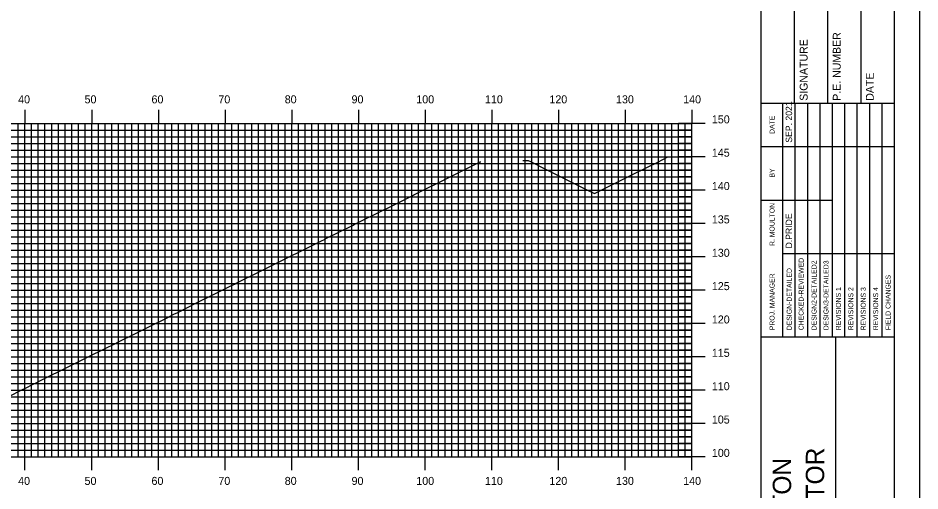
# Model space of a CAD drawing. Extents: x 1684799 to 1685142, y 461260 to 461480.
# Drawn here: x 1685003.7 to 1685138.9, y 461333 to 461403.9 of the extents above; entities that cross this region are included whole.
import ezdxf

# ---------------------------------------------------------------- set-up
doc = ezdxf.new("R2010")
doc.units = 0
for name, color, linetype in [('BORDER', 7, 'Continuous'), ('H_V ANNOTATION', 7, 'Continuous'), ('MAJOR', 7, 'Continuous'), ('MINOR', 7, 'Continuous'), ('PLOT BOUNDARY', 7, 'Continuous'), ('S_Roadway_Centerline', 7, 'Continuous')]:
    doc.layers.add(name, color=color, linetype=linetype)

msp = doc.modelspace()

# ---------------------------------------------------------------- linework, layer by layer
at = {"layer": 'BORDER'}
for p, q in [((1685115.12, 461266.07), (1685115.12, 461476.07)), ((1685120.12, 461391.08), (1685120.12, 461408.37)), ((1685125.12, 461391.08), (1685125.12, 461408.37)), ((1685130.12, 461391.08), (1685130.12, 461408.37)), ((1685115.12, 461391.08), (1685135.12, 461391.08)), ((1685115.12, 461356.08), (1685135.12, 461356.08)), ((1685126.3, 461286.08), (1685126.3, 461356.08))]:
    msp.add_line(p, q, dxfattribs=at)
msp.add_lwpolyline([(1684815.12, 461266.07), (1685135.12, 461266.07), (1685135.12, 461476.07), (1684815.12, 461476.07)], close=True, dxfattribs=at)
for points in [[(1685118.35, 461384.58), (1685118.35, 461391.08)], [(1685120.21, 461356.08), (1685120.21, 461391.08)], [(1685122.07, 461391.08), (1685122.07, 461356.08)], [(1685123.94, 461356.08), (1685123.94, 461391.08)], [(1685125.8, 461356.08), (1685125.8, 461391.08)], [(1685127.66, 461356.08), (1685127.66, 461391.08)], [(1685129.53, 461356.08), (1685129.53, 461391.08)], [(1685131.39, 461356.08), (1685131.39, 461391.08)], [(1685133.25, 461356.08), (1685133.25, 461391.08)], [(1685118.35, 461356.08), (1685118.35, 461389.67)], [(1685115.12, 461384.58), (1685135.12, 461384.58)], [(1685115.12, 461376.58), (1685118.35, 461376.58)], [(1685118.35, 461376.58), (1685125.8, 461376.58)], [(1685118.35, 461368.58), (1685135.12, 461368.58)]]:
    msp.add_lwpolyline(points, dxfattribs=at)
at = {"layer": 'MAJOR'}
for p, q in [((1685004.72, 461390.08), (1685004.72, 461388.07)), ((1685014.72, 461390.08), (1685014.72, 461388.07)), ((1685024.72, 461390.08), (1685024.72, 461388.07)), ((1685034.72, 461390.08), (1685034.72, 461388.07)), ((1685044.72, 461390.08), (1685044.72, 461388.07)), ((1685054.72, 461390.08), (1685054.72, 461388.07)), ((1685064.72, 461390.08), (1685064.72, 461388.07)), ((1685074.72, 461390.08), (1685074.72, 461388.07)), ((1685084.72, 461390.08), (1685084.72, 461388.07)), ((1685094.72, 461390.08), (1685094.72, 461388.07)), ((1685104.72, 461390.08), (1685104.72, 461388.07)), ((1684824.72, 461388.07), (1685104.72, 461388.07)), ((1684824.72, 461388.07), (1685104.72, 461388.07)), ((1685004.72, 461338.07), (1685004.72, 461388.07)), ((1685014.72, 461338.07), (1685014.72, 461388.07)), ((1685024.72, 461338.07), (1685024.72, 461388.07)), ((1685034.72, 461338.07), (1685034.72, 461388.07)), ((1685044.72, 461338.07), (1685044.72, 461388.07)), ((1685054.72, 461338.07), (1685054.72, 461388.07)), ((1685064.72, 461338.07), (1685064.72, 461388.07)), ((1685074.72, 461338.07), (1685074.72, 461388.07)), ((1685084.72, 461338.07), (1685084.72, 461388.07)), ((1685094.72, 461338.07), (1685094.72, 461388.07)), ((1685106.72, 461388.07), (1685102.71, 461388.07)), ((1685104.72, 461338.07), (1685104.72, 461388.07)), ((1685104.72, 461338.07), (1685104.72, 461388.07)), ((1684824.72, 461383.07), (1685104.72, 461383.07)), ((1685106.72, 461383.07), (1685102.71, 461383.07)), ((1684824.72, 461378.07), (1685104.72, 461378.07)), ((1685106.72, 461378.07), (1685102.71, 461378.07)), ((1684824.72, 461373.07), (1685104.72, 461373.07)), ((1685106.72, 461373.07), (1685102.71, 461373.07)), ((1684824.72, 461368.07), (1685104.72, 461368.07)), ((1685106.72, 461368.07), (1685102.71, 461368.07)), ((1684824.72, 461363.07), (1685104.72, 461363.07)), ((1685106.72, 461363.07), (1685102.71, 461363.07)), ((1684824.72, 461358.07), (1685104.72, 461358.07)), ((1685106.72, 461358.07), (1685102.71, 461358.07)), ((1684824.72, 461353.07), (1685104.72, 461353.07)), ((1685106.72, 461353.07), (1685102.71, 461353.07)), ((1684824.72, 461348.07), (1685104.72, 461348.07)), ((1685106.72, 461348.07), (1685102.71, 461348.07)), ((1684824.72, 461343.07), (1685104.72, 461343.07)), ((1685106.72, 461343.07), (1685102.71, 461343.07)), ((1684824.72, 461338.07), (1685104.72, 461338.07)), ((1684824.72, 461338.07), (1685104.72, 461338.07)), ((1685004.72, 461336.07), (1685004.72, 461338.07)), ((1685014.72, 461336.07), (1685014.72, 461338.07)), ((1685024.72, 461336.07), (1685024.72, 461338.07)), ((1685034.72, 461336.07), (1685034.72, 461338.07)), ((1685044.72, 461336.07), (1685044.72, 461338.07)), ((1685054.72, 461336.07), (1685054.72, 461338.07)), ((1685064.72, 461336.07), (1685064.72, 461338.07)), ((1685074.72, 461336.07), (1685074.72, 461338.07)), ((1685084.72, 461336.07), (1685084.72, 461338.07)), ((1685094.72, 461336.07), (1685094.72, 461338.07)), ((1685106.72, 461338.07), (1685102.71, 461338.07)), ((1685104.72, 461336.07), (1685104.72, 461338.07))]:
    msp.add_line(p, q, dxfattribs=at)
at = {"layer": 'MINOR'}
for p, q in [((1685003.72, 461338.07), (1685003.72, 461388.07)), ((1685005.72, 461338.07), (1685005.72, 461388.07)), ((1685006.72, 461338.07), (1685006.72, 461388.07)), ((1685007.72, 461338.07), (1685007.72, 461388.07)), ((1685008.72, 461338.07), (1685008.72, 461388.07)), ((1685009.72, 461338.07), (1685009.72, 461388.07)), ((1685010.72, 461338.07), (1685010.72, 461388.07)), ((1685011.72, 461338.07), (1685011.72, 461388.07)), ((1685012.72, 461338.07), (1685012.72, 461388.07)), ((1685013.72, 461338.07), (1685013.72, 461388.07)), ((1685015.72, 461338.07), (1685015.72, 461388.07)), ((1685016.72, 461338.07), (1685016.72, 461388.07)), ((1685017.72, 461338.07), (1685017.72, 461388.07)), ((1685018.72, 461338.07), (1685018.72, 461388.07)), ((1685019.72, 461338.07), (1685019.72, 461388.07)), ((1685020.72, 461338.07), (1685020.72, 461388.07)), ((1685021.72, 461338.07), (1685021.72, 461388.07)), ((1685022.72, 461338.07), (1685022.72, 461388.07)), ((1685023.72, 461338.07), (1685023.72, 461388.07)), ((1685025.72, 461338.07), (1685025.72, 461388.07)), ((1685026.72, 461338.07), (1685026.72, 461388.07)), ((1685027.72, 461338.07), (1685027.72, 461388.07)), ((1685028.72, 461338.07), (1685028.72, 461388.07)), ((1685029.72, 461338.07), (1685029.72, 461388.07)), ((1685030.72, 461338.07), (1685030.72, 461388.07)), ((1685031.72, 461338.07), (1685031.72, 461388.07)), ((1685032.72, 461338.07), (1685032.72, 461388.07)), ((1685033.72, 461338.07), (1685033.72, 461388.07)), ((1685035.72, 461338.07), (1685035.72, 461388.07)), ((1685036.72, 461338.07), (1685036.72, 461388.07)), ((1685037.72, 461338.07), (1685037.72, 461388.07)), ((1685038.72, 461338.07), (1685038.72, 461388.07)), ((1685039.72, 461338.07), (1685039.72, 461388.07)), ((1685040.72, 461338.07), (1685040.72, 461388.07)), ((1685041.72, 461338.07), (1685041.72, 461388.07)), ((1685042.72, 461338.07), (1685042.72, 461388.07)), ((1685043.72, 461338.07), (1685043.72, 461388.07)), ((1685045.72, 461338.07), (1685045.72, 461388.07)), ((1685046.72, 461338.07), (1685046.72, 461388.07)), ((1685047.72, 461338.07), (1685047.72, 461388.07)), ((1685048.72, 461338.07), (1685048.72, 461388.07)), ((1685049.72, 461338.07), (1685049.72, 461388.07)), ((1685050.72, 461338.07), (1685050.72, 461388.07)), ((1685051.72, 461338.07), (1685051.72, 461388.07)), ((1685052.72, 461338.07), (1685052.72, 461388.07)), ((1685053.72, 461338.07), (1685053.72, 461388.07)), ((1685055.72, 461338.07), (1685055.72, 461388.07)), ((1685056.72, 461338.07), (1685056.72, 461388.07)), ((1685057.72, 461338.07), (1685057.72, 461388.07)), ((1685058.72, 461338.07), (1685058.72, 461388.07)), ((1685059.72, 461338.07), (1685059.72, 461388.07)), ((1685060.72, 461338.07), (1685060.72, 461388.07)), ((1685061.72, 461338.07), (1685061.72, 461388.07)), ((1685062.72, 461338.07), (1685062.72, 461388.07)), ((1685063.72, 461338.07), (1685063.72, 461388.07)), ((1685065.72, 461338.07), (1685065.72, 461388.07)), ((1685066.72, 461338.07), (1685066.72, 461388.07)), ((1685067.72, 461338.07), (1685067.72, 461388.07)), ((1685068.72, 461338.07), (1685068.72, 461388.07)), ((1685069.72, 461338.07), (1685069.72, 461388.07)), ((1685070.72, 461338.07), (1685070.72, 461388.07)), ((1685071.72, 461338.07), (1685071.72, 461388.07)), ((1685072.72, 461338.07), (1685072.72, 461388.07)), ((1685073.72, 461338.07), (1685073.72, 461388.07)), ((1685075.72, 461338.07), (1685075.72, 461388.07)), ((1685076.72, 461338.07), (1685076.72, 461388.07)), ((1685077.72, 461338.07), (1685077.72, 461388.07)), ((1685078.72, 461338.07), (1685078.72, 461388.07)), ((1685079.72, 461338.07), (1685079.72, 461388.07)), ((1685080.72, 461338.07), (1685080.72, 461388.07)), ((1685081.72, 461338.07), (1685081.72, 461388.07)), ((1685082.72, 461338.07), (1685082.72, 461388.07)), ((1685083.72, 461338.07), (1685083.72, 461388.07)), ((1685085.72, 461338.07), (1685085.72, 461388.07)), ((1685086.72, 461338.07), (1685086.72, 461388.07)), ((1685087.72, 461338.07), (1685087.72, 461388.07)), ((1685088.72, 461338.07), (1685088.72, 461388.07)), ((1685089.72, 461338.07), (1685089.72, 461388.07)), ((1685090.72, 461338.07), (1685090.72, 461388.07)), ((1685091.72, 461338.07), (1685091.72, 461388.07)), ((1685092.72, 461338.07), (1685092.72, 461388.07)), ((1685093.72, 461338.07), (1685093.72, 461388.07)), ((1685095.72, 461338.07), (1685095.72, 461388.07)), ((1685096.72, 461338.07), (1685096.72, 461388.07)), ((1685097.72, 461338.07), (1685097.72, 461388.07)), ((1685098.72, 461338.07), (1685098.72, 461388.07)), ((1685099.72, 461338.07), (1685099.72, 461388.07)), ((1685100.72, 461338.07), (1685100.72, 461388.07)), ((1685101.72, 461338.07), (1685101.72, 461388.07)), ((1685102.72, 461338.07), (1685102.72, 461388.07)), ((1685103.72, 461338.07), (1685103.72, 461388.07)), ((1684824.72, 461387.07), (1685104.72, 461387.07)), ((1685104.72, 461387.07), (1685102.71, 461387.07)), ((1684824.72, 461386.07), (1685104.72, 461386.07)), ((1684824.72, 461385.07), (1685104.72, 461385.07)), ((1685104.72, 461386.07), (1685102.71, 461386.07)), ((1685104.72, 461385.07), (1685102.71, 461385.07)), ((1684824.72, 461384.07), (1685104.72, 461384.07)), ((1685104.72, 461384.07), (1685102.71, 461384.07)), ((1684824.72, 461382.07), (1685104.72, 461382.07)), ((1684824.72, 461381.07), (1685104.72, 461381.07)), ((1685104.72, 461382.07), (1685102.71, 461382.07)), ((1685104.72, 461381.07), (1685102.71, 461381.07)), ((1684824.72, 461380.07), (1685104.72, 461380.07)), ((1685104.72, 461380.07), (1685102.71, 461380.07)), ((1684824.72, 461379.07), (1685104.72, 461379.07)), ((1685104.72, 461379.07), (1685102.71, 461379.07)), ((1684824.72, 461377.07), (1685104.72, 461377.07)), ((1685104.72, 461377.07), (1685102.71, 461377.07)), ((1684824.72, 461376.07), (1685104.72, 461376.07)), ((1685104.72, 461376.07), (1685102.71, 461376.07)), ((1684824.72, 461375.07), (1685104.72, 461375.07)), ((1685104.72, 461375.07), (1685102.71, 461375.07)), ((1684824.72, 461374.07), (1685104.72, 461374.07)), ((1685104.72, 461374.07), (1685102.71, 461374.07)), ((1684824.72, 461372.07), (1685104.72, 461372.07)), ((1685104.72, 461372.07), (1685102.71, 461372.07)), ((1684824.72, 461371.07), (1685104.72, 461371.07)), ((1684824.72, 461370.07), (1685104.72, 461370.07)), ((1685104.72, 461371.07), (1685102.71, 461371.07)), ((1685104.72, 461370.07), (1685102.71, 461370.07)), ((1684824.72, 461369.07), (1685104.72, 461369.07)), ((1685104.72, 461369.07), (1685102.71, 461369.07)), ((1684824.72, 461367.07), (1685104.72, 461367.07)), ((1684824.72, 461366.07), (1685104.72, 461366.07)), ((1685104.72, 461367.07), (1685102.71, 461367.07)), ((1685104.72, 461366.07), (1685102.71, 461366.07)), ((1684824.72, 461365.07), (1685104.72, 461365.07)), ((1685104.72, 461365.07), (1685102.71, 461365.07)), ((1684824.72, 461364.07), (1685104.72, 461364.07)), ((1685104.72, 461364.07), (1685102.71, 461364.07)), ((1684824.72, 461362.07), (1685104.72, 461362.07)), ((1685104.72, 461362.07), (1685102.71, 461362.07)), ((1684824.72, 461361.07), (1685104.72, 461361.07)), ((1685104.72, 461361.07), (1685102.71, 461361.07)), ((1684824.72, 461360.07), (1685104.72, 461360.07)), ((1685104.72, 461360.07), (1685102.71, 461360.07)), ((1684824.72, 461359.07), (1685104.72, 461359.07)), ((1685104.72, 461359.07), (1685102.71, 461359.07)), ((1684824.72, 461357.07), (1685104.72, 461357.07)), ((1685104.72, 461357.07), (1685102.71, 461357.07)), ((1684824.72, 461356.07), (1685104.72, 461356.07)), ((1685104.72, 461356.07), (1685102.71, 461356.07)), ((1684824.72, 461355.07), (1685104.72, 461355.07)), ((1684824.72, 461354.07), (1685104.72, 461354.07)), ((1685104.72, 461355.07), (1685102.71, 461355.07)), ((1685104.72, 461354.07), (1685102.71, 461354.07)), ((1684824.72, 461352.07), (1685104.72, 461352.07)), ((1685104.72, 461352.07), (1685102.71, 461352.07)), ((1684824.72, 461351.07), (1685104.72, 461351.07)), ((1684824.72, 461350.07), (1685104.72, 461350.07)), ((1685104.72, 461351.07), (1685102.71, 461351.07)), ((1685104.72, 461350.07), (1685102.71, 461350.07)), ((1684824.72, 461349.07), (1685104.72, 461349.07)), ((1685104.72, 461349.07), (1685102.71, 461349.07)), ((1684824.72, 461347.07), (1685104.72, 461347.07)), ((1685104.72, 461347.07), (1685102.71, 461347.07)), ((1684824.72, 461346.07), (1685104.72, 461346.07)), ((1685104.72, 461346.07), (1685102.71, 461346.07)), ((1684824.72, 461345.07), (1685104.72, 461345.07)), ((1685104.72, 461345.07), (1685102.71, 461345.07)), ((1684824.72, 461344.07), (1685104.72, 461344.07)), ((1685104.72, 461344.07), (1685102.71, 461344.07)), ((1684824.72, 461342.07), (1685104.72, 461342.07)), ((1685104.72, 461342.07), (1685102.71, 461342.07)), ((1684824.72, 461341.07), (1685104.72, 461341.07)), ((1685104.72, 461341.07), (1685102.71, 461341.07)), ((1684824.72, 461340.07), (1685104.72, 461340.07)), ((1684824.72, 461339.07), (1685104.72, 461339.07)), ((1685104.72, 461340.07), (1685102.71, 461340.07)), ((1685104.72, 461339.07), (1685102.71, 461339.07))]:
    msp.add_line(p, q, dxfattribs=at)
at = {"layer": 'PLOT BOUNDARY'}
msp.add_lwpolyline([(1684798.93, 461259.95), (1685138.93, 461259.95), (1685138.93, 461479.95), (1684798.93, 461479.95)], close=True, dxfattribs=at)
at = {"layer": 'S_Roadway_Centerline'}
for points in [[(1685002.19, 461347.08), (1685004.33, 461348.15), (1685004.71, 461348.34), (1685006.05, 461349), (1685006.38, 461349.17), (1685006.87, 461349.41), (1685008.06, 461350), (1685010.41, 461351.17), (1685013.69, 461352.81), (1685014.2, 461353.06), (1685016.73, 461354.32), (1685018.18, 461355.04), (1685018.64, 461355.27), (1685021.37, 461356.63), (1685022.67, 461357.27), (1685023.08, 461357.48), (1685026.02, 461358.94), (1685027.16, 461359.51), (1685027.53, 461359.69), (1685030.65, 461361.24), (1685031.65, 461361.74), (1685031.97, 461361.9), (1685035.29, 461363.55), (1685036.14, 461363.97), (1685036.41, 461364.11), (1685039.92, 461365.85), (1685040.63, 461366.21), (1685040.86, 461366.32), (1685044.55, 461368.16), (1685045.12, 461368.44), (1685045.3, 461368.53), (1685049.18, 461370.46), (1685049.61, 461370.68), (1685049.75, 461370.74), (1685053.81, 461372.76), (1685054.1, 461372.91), (1685054.19, 461372.96), (1685058.43, 461375.06), (1685058.59, 461375.14), (1685058.87, 461375.28), (1685063.07, 461377.37), (1685063.1, 461377.39), (1685063.11, 461377.39), (1685063.13, 461377.4), (1685063.94, 461377.81), (1685067.56, 461379.62), (1685067.65, 461379.66), (1685067.77, 461379.72), (1685072.97, 461382.32), (1685073.07, 461382.32), (1685073.07, 461382.32)], [(1685079.4, 461382.49), (1685079.46, 461382.49), (1685080.14, 461382.51), (1685080.17, 461382.51), (1685080.51, 461382.34), (1685082.69, 461381.25), (1685089.09, 461378.05), (1685090.11, 461377.54), (1685093.24, 461379.1), (1685095.61, 461380.28), (1685098.07, 461381.51), (1685099.6, 461382.27), (1685101.13, 461383.03), (1685101.15, 461383.03), (1685101.65, 461383.03), (1685101.65, 461383.03)]]:
    msp.add_lwpolyline(points, dxfattribs=at)

# ---------------------------------------------------------------- texts
at = {"layer": 'BORDER'}
for s, height, p in [('P.E. NUMBER', 1.1811, (1685127.04, 461391.46)), ('SIGNATURE', 1.181, (1685122.08, 461391.46)), ('DATE', 1.181, (1685132, 461391.46)), ('SEP. 2021', 0.969, (1685119.76, 461385.17)), ('DATE', 0.743, (1685117.12, 461386.49)), ('BY', 0.743, (1685117.12, 461379.95)), ('R. MOULTON', 0.745, (1685117.12, 461369.68)), ('D.PRIDE', 0.969, (1685119.76, 461369.32)), ('CHECKED-REVIEWED', 0.7455, (1685121.48, 461357.05)), ('DESIGN-DETAILED', 0.7455, (1685119.69, 461357.05)), ('DESIGN2-DETAILED2', 0.7455, (1685123.42, 461357.05)), ('DESIGN3-DETAILED3', 0.7455, (1685125.21, 461357.05)), ('PROJ. MANAGER', 0.7455, (1685117.12, 461357.05)), ('FIELD CHANGES', 0.7455, (1685134.52, 461357.05)), ('REVISIONS 1', 0.7455, (1685127.07, 461357.05)), ('REVISIONS 2', 0.7455, (1685128.93, 461357.05)), ('REVISIONS 3', 0.7455, (1685130.8, 461357.05)), ('REVISIONS 4', 0.7455, (1685132.66, 461357.05)), ('1-395/ROUTE 9 CONNECTOR', 2.7557, (1685124.57, 461288.27)), ('BREWER TO EDDINGTON', 2.7557, (1685119.61, 461292.48))]:
    msp.add_text(s, height=height, rotation=90, dxfattribs=at).set_placement(p)
at = {"layer": 'H_V ANNOTATION'}
for s, p in [('40', (1685003.69, 461391.07)), ('50', (1685013.65, 461391.07)), ('60', (1685023.69, 461391.07)), ('70', (1685033.72, 461391.07)), ('80', (1685043.67, 461391.07)), ('90', (1685053.69, 461391.07)), ('100', (1685063.4, 461391.07)), ('110', (1685073.7, 461391.07)), ('120', (1685083.36, 461391.07)), ('130', (1685093.35, 461391.07)), ('140', (1685103.42, 461391.07)), ('150', (1685107.72, 461388.07)), ('145', (1685107.72, 461383.07)), ('140', (1685107.72, 461378.07)), ('135', (1685107.72, 461373.07)), ('130', (1685107.72, 461368.07)), ('125', (1685107.72, 461363.07)), ('120', (1685107.72, 461358.07)), ('115', (1685107.72, 461353.07)), ('110', (1685107.72, 461348.07)), ('105', (1685107.72, 461343.07)), ('100', (1685107.72, 461338.07)), ('40', (1685003.69, 461333.87)), ('50', (1685013.65, 461333.87)), ('60', (1685023.69, 461333.87)), ('70', (1685033.72, 461333.87)), ('80', (1685043.67, 461333.87)), ('90', (1685053.69, 461333.87)), ('100', (1685063.4, 461333.87)), ('110', (1685073.7, 461333.87)), ('120', (1685083.36, 461333.87)), ('130', (1685093.35, 461333.87)), ('140', (1685103.42, 461333.87))]:
    msp.add_text(s, height=1.2, dxfattribs=at).set_placement(p)

doc.saveas('drawing.dxf')
